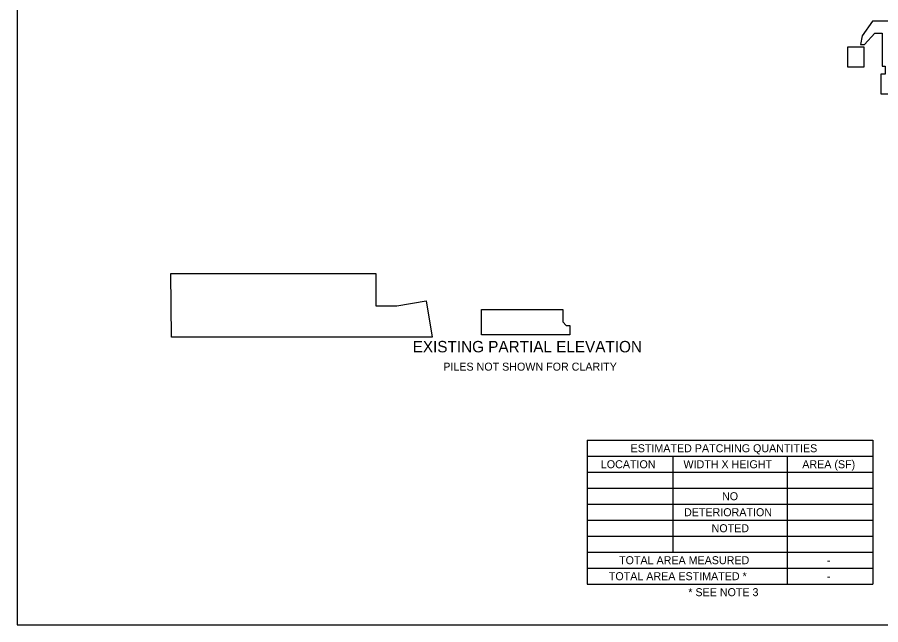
# Model space of a CAD drawing. Extents: x 100 to 130.5, y 100 to 121.
# Drawn here: x 100 to 115.11, y 100 to 110.64 of the extents above; entities that cross this region are included whole.
import ezdxf

# ---------------------------------------------------------------- set-up
doc = ezdxf.new("R2010")
doc.units = 0
for name, color, linetype in [('BR_P_Gen_Text', 7, 'Continuous'), ('SC_Scratch1', 7, 'Continuous'), ('SH_Masking', 7, 'Continuous')]:
    doc.layers.add(name, color=color, linetype=linetype)

msp = doc.modelspace()

# ---------------------------------------------------------------- linework, layer by layer
at = {"layer": 'BR_P_Gen_Text'}
for p, q in [((109.97, 103.23), (109.97, 100.71)), ((109.97, 103.23), (114.97, 103.23)), ((114.97, 103.23), (114.97, 100.71)), ((109.97, 102.95), (114.97, 102.95)), ((111.47, 102.95), (111.47, 101.27)), ((113.47, 102.95), (113.47, 100.71)), ((109.97, 102.67), (114.97, 102.67)), ((109.97, 102.39), (114.97, 102.39)), ((109.97, 102.11), (114.97, 102.11)), ((109.97, 101.83), (114.97, 101.83)), ((109.97, 101.55), (114.97, 101.55)), ((109.97, 101.27), (114.97, 101.27)), ((109.97, 100.99), (114.97, 100.99)), ((109.97, 100.71), (114.97, 100.71))]:
    msp.add_line(p, q, dxfattribs=at)
at = {"layer": 'SC_Scratch1'}
msp.add_lwpolyline([(100, 100), (130.5, 100), (130.5, 121), (100, 121)], close=True, dxfattribs=at)
at = {"layer": 'SH_Masking'}
for points in [[(114.755, 110.157), (114.827, 110.157), (115.005, 110.358), (115.137, 110.358), (115.137, 109.779), (115.187, 109.779), (115.187, 109.642), (115.114, 109.642), (115.114, 109.296), (115.488, 109.296), (115.488, 110.567), (115.146, 110.567), (114.966, 110.568), (114.782, 110.312)], [(114.536, 110.121), (114.814, 110.121), (114.814, 109.761), (114.536, 109.761)], [(102.686, 106.152), (106.273, 106.152), (106.273, 105.582), (106.643, 105.582), (107.156, 105.674), (107.262, 105.034), (102.7, 105.034)], [(108.124, 105.521), (109.546, 105.521), (109.546, 105.306), (109.604, 105.237), (109.67, 105.237), (109.67, 105.077), (108.124, 105.077)]]:
    msp.add_lwpolyline(points, close=True, dxfattribs=at)

# ---------------------------------------------------------------- texts
at = {"layer": 'BR_P_Gen_Text'}
for s, height, p in [('EXISTING PARTIAL ELEVATION', 0.2, (106.919, 104.769)), ('PILES NOT SHOWN FOR CLARITY', 0.14, (107.455, 104.449)), ('ESTIMATED PATCHING QUANTITIES', 0.14, (110.733, 103.02)), ('LOCATION', 0.14, (110.212, 102.74)), ('WIDTH X HEIGHT', 0.14, (111.658, 102.74)), ('AREA (SF)', 0.14, (113.737, 102.74)), ('NO', 0.14, (112.333, 102.18)), ('DETERIORATION', 0.14, (111.668, 101.9)), ('NOTED', 0.14, (112.15, 101.62)), ('TOTAL AREA MEASURED', 0.14, (110.531, 101.06)), ('-', 0.14, (114.167, 101.06)), ('TOTAL AREA ESTIMATED *', 0.14, (110.352, 100.78)), ('-', 0.14, (114.167, 100.78)), ('* SEE NOTE 3', 0.14, (111.743, 100.5))]:
    msp.add_text(s, height=height, dxfattribs=at).set_placement(p)

doc.saveas('drawing.dxf')
